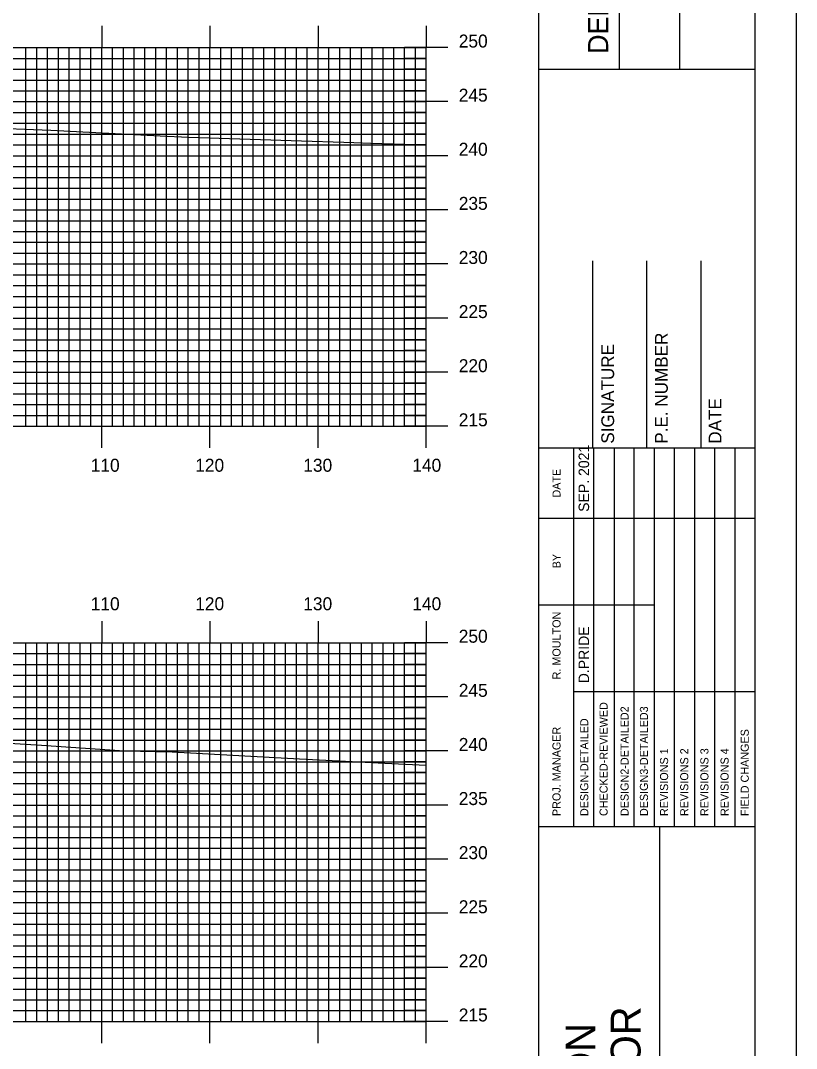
# Model space of a CAD drawing. Extents: x 1816883 to 1817226, y 442591 to 442811.
# Drawn here: x 1817151.1 to 1817222.8, y 442666.2 to 442761.2 of the extents above; entities that cross this region are included whole.
import ezdxf

# ---------------------------------------------------------------- set-up
doc = ezdxf.new("R2010")
doc.units = 0
for name, color, linetype in [('BORDER', 7, 'Continuous'), ('H_V ANNOTATION', 7, 'Continuous'), ('MAJOR', 7, 'Continuous'), ('MINOR', 7, 'Continuous'), ('PLOT BOUNDARY', 7, 'Continuous'), ('S_Roadway_Centerline', 7, 'Continuous')]:
    doc.layers.add(name, color=color, linetype=linetype)

msp = doc.modelspace()

# ---------------------------------------------------------------- linework, layer by layer
at = {"layer": 'BORDER'}
for p, q in [((1817198.986, 442596.665), (1817198.986, 442806.665)), ((1817206.443, 442756.659), (1817206.443, 442806.659)), ((1817212.033, 442756.659), (1817212.033, 442806.659)), ((1817198.988, 442756.653), (1817218.986, 442756.653)), ((1817203.986, 442721.671), (1817203.986, 442738.966)), ((1817208.986, 442721.671), (1817208.986, 442738.966)), ((1817213.986, 442721.671), (1817213.986, 442738.966)), ((1817198.986, 442721.671), (1817218.986, 442721.671)), ((1817198.986, 442686.671), (1817218.986, 442686.671)), ((1817210.168, 442616.671), (1817210.168, 442686.671))]:
    msp.add_line(p, q, dxfattribs=at)
msp.add_lwpolyline([(1816898.986, 442596.665), (1817218.986, 442596.665), (1817218.986, 442806.665), (1816898.986, 442806.665)], close=True, dxfattribs=at)
for points in [[(1817202.216, 442715.171), (1817202.216, 442721.671)], [(1817204.081, 442686.677), (1817204.081, 442721.671)], [(1817205.944, 442721.671), (1817205.944, 442686.677)], [(1817207.808, 442686.677), (1817207.808, 442721.671)], [(1817209.671, 442686.677), (1817209.671, 442721.671)], [(1817211.534, 442686.677), (1817211.534, 442721.671)], [(1817213.398, 442686.677), (1817213.398, 442721.671)], [(1817215.261, 442686.677), (1817215.261, 442721.671)], [(1817217.125, 442686.677), (1817217.125, 442721.671)], [(1817202.218, 442686.677), (1817202.218, 442720.259)], [(1817198.986, 442715.171), (1817218.986, 442715.171)], [(1817198.986, 442707.171), (1817202.218, 442707.171)], [(1817202.216, 442707.171), (1817209.669, 442707.171)], [(1817202.216, 442699.171), (1817218.986, 442699.171)]]:
    msp.add_lwpolyline(points, dxfattribs=at)
at = {"layer": 'MAJOR'}
for p, q in [((1817158.586, 442760.669), (1817158.586, 442758.665)), ((1817168.586, 442760.669), (1817168.586, 442758.665)), ((1817178.586, 442760.669), (1817178.586, 442758.665)), ((1817188.586, 442760.669), (1817188.586, 442758.665)), ((1816908.586, 442758.665), (1817188.586, 442758.665)), ((1816908.586, 442758.665), (1817188.586, 442758.665)), ((1817158.586, 442723.665), (1817158.586, 442758.665)), ((1817168.586, 442723.665), (1817168.586, 442758.665)), ((1817178.586, 442723.665), (1817178.586, 442758.665)), ((1817190.59, 442758.665), (1817186.582, 442758.665)), ((1817188.586, 442723.665), (1817188.586, 442758.665)), ((1817188.586, 442723.665), (1817188.586, 442758.665)), ((1816908.586, 442753.665), (1817188.586, 442753.665)), ((1817190.59, 442753.665), (1817186.582, 442753.665)), ((1816908.586, 442748.665), (1817188.586, 442748.665)), ((1817190.59, 442748.665), (1817186.582, 442748.665)), ((1816908.586, 442743.665), (1817188.586, 442743.665)), ((1817190.59, 442743.665), (1817186.582, 442743.665)), ((1816908.586, 442738.665), (1817188.586, 442738.665)), ((1817190.59, 442738.665), (1817186.582, 442738.665)), ((1816908.586, 442733.665), (1817188.586, 442733.665)), ((1817190.59, 442733.665), (1817186.582, 442733.665)), ((1816908.586, 442728.665), (1817188.586, 442728.665)), ((1817190.59, 442728.665), (1817186.582, 442728.665)), ((1816908.586, 442723.665), (1817188.586, 442723.665)), ((1816908.586, 442723.665), (1817188.586, 442723.665)), ((1817158.586, 442721.661), (1817158.586, 442723.665)), ((1817168.586, 442721.661), (1817168.586, 442723.665)), ((1817178.586, 442721.661), (1817178.586, 442723.665)), ((1817190.59, 442723.665), (1817186.582, 442723.665)), ((1817188.586, 442721.661), (1817188.586, 442723.665)), ((1817158.586, 442705.669), (1817158.586, 442703.665)), ((1817168.586, 442705.669), (1817168.586, 442703.665)), ((1817178.586, 442705.669), (1817178.586, 442703.665)), ((1817188.586, 442705.669), (1817188.586, 442703.665)), ((1816908.586, 442703.665), (1817188.586, 442703.665)), ((1816908.586, 442703.665), (1817188.586, 442703.665)), ((1817158.586, 442668.665), (1817158.586, 442703.665)), ((1817168.586, 442668.665), (1817168.586, 442703.665)), ((1817178.586, 442668.665), (1817178.586, 442703.665)), ((1817190.59, 442703.665), (1817186.582, 442703.665)), ((1817188.586, 442668.665), (1817188.586, 442703.665)), ((1817188.586, 442668.665), (1817188.586, 442703.665)), ((1816908.586, 442698.665), (1817188.586, 442698.665)), ((1817190.59, 442698.665), (1817186.582, 442698.665)), ((1816908.586, 442693.665), (1817188.586, 442693.665)), ((1817190.59, 442693.665), (1817186.582, 442693.665)), ((1816908.586, 442688.665), (1817188.586, 442688.665)), ((1817190.59, 442688.665), (1817186.582, 442688.665)), ((1816908.586, 442683.665), (1817188.586, 442683.665)), ((1817190.59, 442683.665), (1817186.582, 442683.665)), ((1816908.586, 442678.665), (1817188.586, 442678.665)), ((1817190.59, 442678.665), (1817186.582, 442678.665)), ((1816908.586, 442673.665), (1817188.586, 442673.665)), ((1817190.59, 442673.665), (1817186.582, 442673.665)), ((1816908.586, 442668.665), (1817188.586, 442668.665)), ((1816908.586, 442668.665), (1817188.586, 442668.665)), ((1817158.586, 442666.661), (1817158.586, 442668.665)), ((1817168.586, 442666.661), (1817168.586, 442668.665)), ((1817178.586, 442666.661), (1817178.586, 442668.665)), ((1817190.59, 442668.665), (1817186.582, 442668.665)), ((1817188.586, 442666.661), (1817188.586, 442668.665))]:
    msp.add_line(p, q, dxfattribs=at)
at = {"layer": 'MINOR'}
for p, q in [((1817151.586, 442723.665), (1817151.586, 442758.665)), ((1817152.586, 442723.665), (1817152.586, 442758.665)), ((1817153.586, 442723.665), (1817153.586, 442758.665)), ((1817154.586, 442723.665), (1817154.586, 442758.665)), ((1817155.586, 442723.665), (1817155.586, 442758.665)), ((1817156.586, 442723.665), (1817156.586, 442758.665)), ((1817157.586, 442723.665), (1817157.586, 442758.665)), ((1817159.586, 442723.665), (1817159.586, 442758.665)), ((1817160.586, 442723.665), (1817160.586, 442758.665)), ((1817161.586, 442723.665), (1817161.586, 442758.665)), ((1817162.586, 442723.665), (1817162.586, 442758.665)), ((1817163.586, 442723.665), (1817163.586, 442758.665)), ((1817164.586, 442723.665), (1817164.586, 442758.665)), ((1817165.586, 442723.665), (1817165.586, 442758.665)), ((1817166.586, 442723.665), (1817166.586, 442758.665)), ((1817167.586, 442723.665), (1817167.586, 442758.665)), ((1817169.586, 442723.665), (1817169.586, 442758.665)), ((1817170.586, 442723.665), (1817170.586, 442758.665)), ((1817171.586, 442723.665), (1817171.586, 442758.665)), ((1817172.586, 442723.665), (1817172.586, 442758.665)), ((1817173.586, 442723.665), (1817173.586, 442758.665)), ((1817174.586, 442723.665), (1817174.586, 442758.665)), ((1817175.586, 442723.665), (1817175.586, 442758.665)), ((1817176.586, 442723.665), (1817176.586, 442758.665)), ((1817177.586, 442723.665), (1817177.586, 442758.665)), ((1817179.586, 442723.665), (1817179.586, 442758.665)), ((1817180.586, 442723.665), (1817180.586, 442758.665)), ((1817181.586, 442723.665), (1817181.586, 442758.665)), ((1817182.586, 442723.665), (1817182.586, 442758.665)), ((1817183.586, 442723.665), (1817183.586, 442758.665)), ((1817184.586, 442723.665), (1817184.586, 442758.665)), ((1817185.586, 442723.665), (1817185.586, 442758.665)), ((1817186.586, 442723.665), (1817186.586, 442758.665)), ((1817187.586, 442723.665), (1817187.586, 442758.665)), ((1816908.586, 442757.665), (1817188.586, 442757.665)), ((1817188.586, 442757.665), (1817186.582, 442757.665)), ((1816908.586, 442756.665), (1817188.586, 442756.665)), ((1817188.586, 442756.665), (1817186.582, 442756.665)), ((1816908.586, 442755.665), (1817188.586, 442755.665)), ((1817188.586, 442755.665), (1817186.582, 442755.665)), ((1816908.586, 442754.665), (1817188.586, 442754.665)), ((1817188.586, 442754.665), (1817186.582, 442754.665)), ((1816908.586, 442752.665), (1817188.586, 442752.665)), ((1817188.586, 442752.665), (1817186.582, 442752.665)), ((1816908.586, 442751.665), (1817188.586, 442751.665)), ((1817188.586, 442751.665), (1817186.582, 442751.665)), ((1816908.586, 442750.665), (1817188.586, 442750.665)), ((1817188.586, 442750.665), (1817186.582, 442750.665)), ((1816908.586, 442749.665), (1817188.586, 442749.665)), ((1817188.586, 442749.665), (1817186.582, 442749.665)), ((1816908.586, 442747.665), (1817188.586, 442747.665)), ((1817188.586, 442747.665), (1817186.582, 442747.665)), ((1816908.586, 442746.665), (1817188.586, 442746.665)), ((1817188.586, 442746.665), (1817186.582, 442746.665)), ((1816908.586, 442745.665), (1817188.586, 442745.665)), ((1817188.586, 442745.665), (1817186.582, 442745.665)), ((1816908.586, 442744.665), (1817188.586, 442744.665)), ((1817188.586, 442744.665), (1817186.582, 442744.665)), ((1816908.586, 442742.665), (1817188.586, 442742.665)), ((1817188.586, 442742.665), (1817186.582, 442742.665)), ((1816908.586, 442741.665), (1817188.586, 442741.665)), ((1817188.586, 442741.665), (1817186.582, 442741.665)), ((1816908.586, 442740.665), (1817188.586, 442740.665)), ((1817188.586, 442740.665), (1817186.582, 442740.665)), ((1816908.586, 442739.665), (1817188.586, 442739.665)), ((1817188.586, 442739.665), (1817186.582, 442739.665)), ((1816908.586, 442737.665), (1817188.586, 442737.665)), ((1817188.586, 442737.665), (1817186.582, 442737.665)), ((1816908.586, 442736.665), (1817188.586, 442736.665)), ((1817188.586, 442736.665), (1817186.582, 442736.665)), ((1816908.586, 442735.665), (1817188.586, 442735.665)), ((1817188.586, 442735.665), (1817186.582, 442735.665)), ((1816908.586, 442734.665), (1817188.586, 442734.665)), ((1817188.586, 442734.665), (1817186.582, 442734.665)), ((1816908.586, 442732.665), (1817188.586, 442732.665)), ((1817188.586, 442732.665), (1817186.582, 442732.665)), ((1816908.586, 442731.665), (1817188.586, 442731.665)), ((1817188.586, 442731.665), (1817186.582, 442731.665)), ((1816908.586, 442730.665), (1817188.586, 442730.665)), ((1817188.586, 442730.665), (1817186.582, 442730.665)), ((1816908.586, 442729.665), (1817188.586, 442729.665)), ((1817188.586, 442729.665), (1817186.582, 442729.665)), ((1816908.586, 442727.665), (1817188.586, 442727.665)), ((1817188.586, 442727.665), (1817186.582, 442727.665)), ((1816908.586, 442726.665), (1817188.586, 442726.665)), ((1817188.586, 442726.665), (1817186.582, 442726.665)), ((1816908.586, 442725.665), (1817188.586, 442725.665)), ((1817188.586, 442725.665), (1817186.582, 442725.665)), ((1816908.586, 442724.665), (1817188.586, 442724.665)), ((1817188.586, 442724.665), (1817186.582, 442724.665)), ((1817151.586, 442668.665), (1817151.586, 442703.665)), ((1817152.586, 442668.665), (1817152.586, 442703.665)), ((1817153.586, 442668.665), (1817153.586, 442703.665)), ((1817154.586, 442668.665), (1817154.586, 442703.665)), ((1817155.586, 442668.665), (1817155.586, 442703.665)), ((1817156.586, 442668.665), (1817156.586, 442703.665)), ((1817157.586, 442668.665), (1817157.586, 442703.665)), ((1817159.586, 442668.665), (1817159.586, 442703.665)), ((1817160.586, 442668.665), (1817160.586, 442703.665)), ((1817161.586, 442668.665), (1817161.586, 442703.665)), ((1817162.586, 442668.665), (1817162.586, 442703.665)), ((1817163.586, 442668.665), (1817163.586, 442703.665)), ((1817164.586, 442668.665), (1817164.586, 442703.665)), ((1817165.586, 442668.665), (1817165.586, 442703.665)), ((1817166.586, 442668.665), (1817166.586, 442703.665)), ((1817167.586, 442668.665), (1817167.586, 442703.665)), ((1817169.586, 442668.665), (1817169.586, 442703.665)), ((1817170.586, 442668.665), (1817170.586, 442703.665)), ((1817171.586, 442668.665), (1817171.586, 442703.665)), ((1817172.586, 442668.665), (1817172.586, 442703.665)), ((1817173.586, 442668.665), (1817173.586, 442703.665)), ((1817174.586, 442668.665), (1817174.586, 442703.665)), ((1817175.586, 442668.665), (1817175.586, 442703.665)), ((1817176.586, 442668.665), (1817176.586, 442703.665)), ((1817177.586, 442668.665), (1817177.586, 442703.665)), ((1817179.586, 442668.665), (1817179.586, 442703.665)), ((1817180.586, 442668.665), (1817180.586, 442703.665)), ((1817181.586, 442668.665), (1817181.586, 442703.665)), ((1817182.586, 442668.665), (1817182.586, 442703.665)), ((1817183.586, 442668.665), (1817183.586, 442703.665)), ((1817184.586, 442668.665), (1817184.586, 442703.665)), ((1817185.586, 442668.665), (1817185.586, 442703.665)), ((1817186.586, 442668.665), (1817186.586, 442703.665)), ((1817187.586, 442668.665), (1817187.586, 442703.665)), ((1816908.586, 442702.665), (1817188.586, 442702.665)), ((1817188.586, 442702.665), (1817186.582, 442702.665)), ((1816908.586, 442701.665), (1817188.586, 442701.665)), ((1817188.586, 442701.665), (1817186.582, 442701.665)), ((1816908.586, 442700.665), (1817188.586, 442700.665)), ((1817188.586, 442700.665), (1817186.582, 442700.665)), ((1816908.586, 442699.665), (1817188.586, 442699.665)), ((1817188.586, 442699.665), (1817186.582, 442699.665)), ((1816908.586, 442697.665), (1817188.586, 442697.665)), ((1817188.586, 442697.665), (1817186.582, 442697.665)), ((1816908.586, 442696.665), (1817188.586, 442696.665)), ((1817188.586, 442696.665), (1817186.582, 442696.665)), ((1816908.586, 442695.665), (1817188.586, 442695.665)), ((1817188.586, 442695.665), (1817186.582, 442695.665)), ((1816908.586, 442694.665), (1817188.586, 442694.665)), ((1817188.586, 442694.665), (1817186.582, 442694.665)), ((1816908.586, 442692.665), (1817188.586, 442692.665)), ((1817188.586, 442692.665), (1817186.582, 442692.665)), ((1816908.586, 442691.665), (1817188.586, 442691.665)), ((1817188.586, 442691.665), (1817186.582, 442691.665)), ((1816908.586, 442690.665), (1817188.586, 442690.665)), ((1817188.586, 442690.665), (1817186.582, 442690.665)), ((1816908.586, 442689.665), (1817188.586, 442689.665)), ((1817188.586, 442689.665), (1817186.582, 442689.665)), ((1816908.586, 442687.665), (1817188.586, 442687.665)), ((1817188.586, 442687.665), (1817186.582, 442687.665)), ((1816908.586, 442686.665), (1817188.586, 442686.665)), ((1817188.586, 442686.665), (1817186.582, 442686.665)), ((1816908.586, 442685.665), (1817188.586, 442685.665)), ((1817188.586, 442685.665), (1817186.582, 442685.665)), ((1816908.586, 442684.665), (1817188.586, 442684.665)), ((1817188.586, 442684.665), (1817186.582, 442684.665)), ((1816908.586, 442682.665), (1817188.586, 442682.665)), ((1817188.586, 442682.665), (1817186.582, 442682.665)), ((1816908.586, 442681.665), (1817188.586, 442681.665)), ((1817188.586, 442681.665), (1817186.582, 442681.665)), ((1816908.586, 442680.665), (1817188.586, 442680.665)), ((1817188.586, 442680.665), (1817186.582, 442680.665)), ((1816908.586, 442679.665), (1817188.586, 442679.665)), ((1817188.586, 442679.665), (1817186.582, 442679.665)), ((1816908.586, 442677.665), (1817188.586, 442677.665)), ((1817188.586, 442677.665), (1817186.582, 442677.665)), ((1816908.586, 442676.665), (1817188.586, 442676.665)), ((1817188.586, 442676.665), (1817186.582, 442676.665)), ((1816908.586, 442675.665), (1817188.586, 442675.665)), ((1817188.586, 442675.665), (1817186.582, 442675.665)), ((1816908.586, 442674.665), (1817188.586, 442674.665)), ((1817188.586, 442674.665), (1817186.582, 442674.665)), ((1816908.586, 442672.665), (1817188.586, 442672.665)), ((1817188.586, 442672.665), (1817186.582, 442672.665)), ((1816908.586, 442671.665), (1817188.586, 442671.665)), ((1817188.586, 442671.665), (1817186.582, 442671.665)), ((1816908.586, 442670.665), (1817188.586, 442670.665)), ((1817188.586, 442670.665), (1817186.582, 442670.665)), ((1816908.586, 442669.665), (1817188.586, 442669.665)), ((1817188.586, 442669.665), (1817186.582, 442669.665))]:
    msp.add_line(p, q, dxfattribs=at)
at = {"layer": 'PLOT BOUNDARY'}
msp.add_lwpolyline([(1816882.799, 442590.547), (1817222.799, 442590.547), (1817222.799, 442810.547), (1816882.799, 442810.547)], close=True, dxfattribs=at)
at = {"layer": 'S_Roadway_Centerline'}
for points in [[(1817079.033, 442752.196), (1817086.697, 442752.229), (1817097.526, 442752.144), (1817113.075, 442751.766), (1817113.174, 442751.765), (1817113.244, 442751.765), (1817113.603, 442751.773), (1817127.715, 442752.07), (1817131.091, 442751.954), (1817135.838, 442751.813), (1817147.472, 442751.265), (1817153.88, 442751.03), (1817163.982, 442750.508), (1817166.615, 442750.368), (1817177.059, 442750.041), (1817180.959, 442749.914), (1817181.886, 442749.899), (1817183.457, 442749.83), (1817188.586, 442749.673)], [(1817075.827, 442696.557), (1817084.589, 442696.386), (1817093.06, 442696.358), (1817098.409, 442696.153), (1817110.047, 442695.953), (1817111.593, 442695.935), (1817126.859, 442695.336), (1817139.346, 442694.895), (1817144.101, 442694.749), (1817153.023, 442694.193), (1817160.683, 442693.664), (1817165.109, 442693.591), (1817176.869, 442692.94), (1817184.756, 442692.536), (1817188.586, 442692.36)]]:
    msp.add_lwpolyline(points, dxfattribs=at)

# ---------------------------------------------------------------- texts
at = {"layer": 'BORDER'}
for s, height, p in [('DEPARTMENT OF TRANSPORTATION', 1.86351, (1817205.4, 442758.077)), ('P.E. NUMBER', 1.1811, (1817210.908, 442722.055)), ('SIGNATURE', 1.1811, (1817205.947, 442722.055)), ('DATE', 1.1811, (1817215.868, 442722.055)), ('SEP. 2021', 0.9691, (1817203.633, 442715.762)), ('DATE', 0.7428, (1817200.995, 442717.083)), ('BY', 0.7428, (1817200.995, 442710.541)), ('R. MOULTON', 0.7455, (1817200.996, 442700.276)), ('D.PRIDE', 0.9691, (1817203.633, 442699.917)), ('CHECKED-REVIEWED', 0.7455, (1817205.348, 442687.647)), ('DESIGN2-DETAILED2', 0.7455, (1817207.286, 442687.647)), ('DESIGN3-DETAILED3', 0.7455, (1817209.075, 442687.647)), ('DESIGN-DETAILED', 0.7455, (1817203.559, 442687.647)), ('PROJ. MANAGER', 0.7455, (1817200.995, 442687.647)), ('FIELD CHANGES', 0.7455, (1817218.392, 442687.647)), ('REVISIONS 1', 0.7455, (1817210.938, 442687.647)), ('REVISIONS 2', 0.7455, (1817212.802, 442687.647)), ('REVISIONS 3', 0.7455, (1817214.665, 442687.647)), ('REVISIONS 4', 0.7455, (1817216.528, 442687.647)), ('1-395/ROUTE 9 CONNECTOR', 2.75575, (1817208.39, 442618.865)), ('BREWER TO EDDINGTON', 2.75575, (1817204.21, 442623.074))]:
    msp.add_text(s, height=height, rotation=90, dxfattribs=at).set_placement(p)
at = {"layer": 'H_V ANNOTATION'}
for s, p in [('250', (1817191.586, 442758.665)), ('245', (1817191.586, 442753.665)), ('240', (1817191.586, 442748.665)), ('235', (1817191.586, 442743.665)), ('230', (1817191.586, 442738.665)), ('225', (1817191.586, 442733.665)), ('220', (1817191.586, 442728.665)), ('215', (1817191.586, 442723.665)), ('110', (1817157.569, 442719.465)), ('120', (1817167.227, 442719.465)), ('130', (1817177.216, 442719.465)), ('140', (1817187.291, 442719.465)), ('110', (1817157.569, 442706.665)), ('120', (1817167.227, 442706.665)), ('130', (1817177.216, 442706.665)), ('140', (1817187.291, 442706.665)), ('250', (1817191.586, 442703.665)), ('245', (1817191.586, 442698.665)), ('240', (1817191.586, 442693.665)), ('235', (1817191.586, 442688.665)), ('230', (1817191.586, 442683.665)), ('225', (1817191.586, 442678.665)), ('220', (1817191.586, 442673.665)), ('215', (1817191.586, 442668.665))]:
    msp.add_text(s, height=1.2, dxfattribs=at).set_placement(p)

doc.saveas('drawing.dxf')
